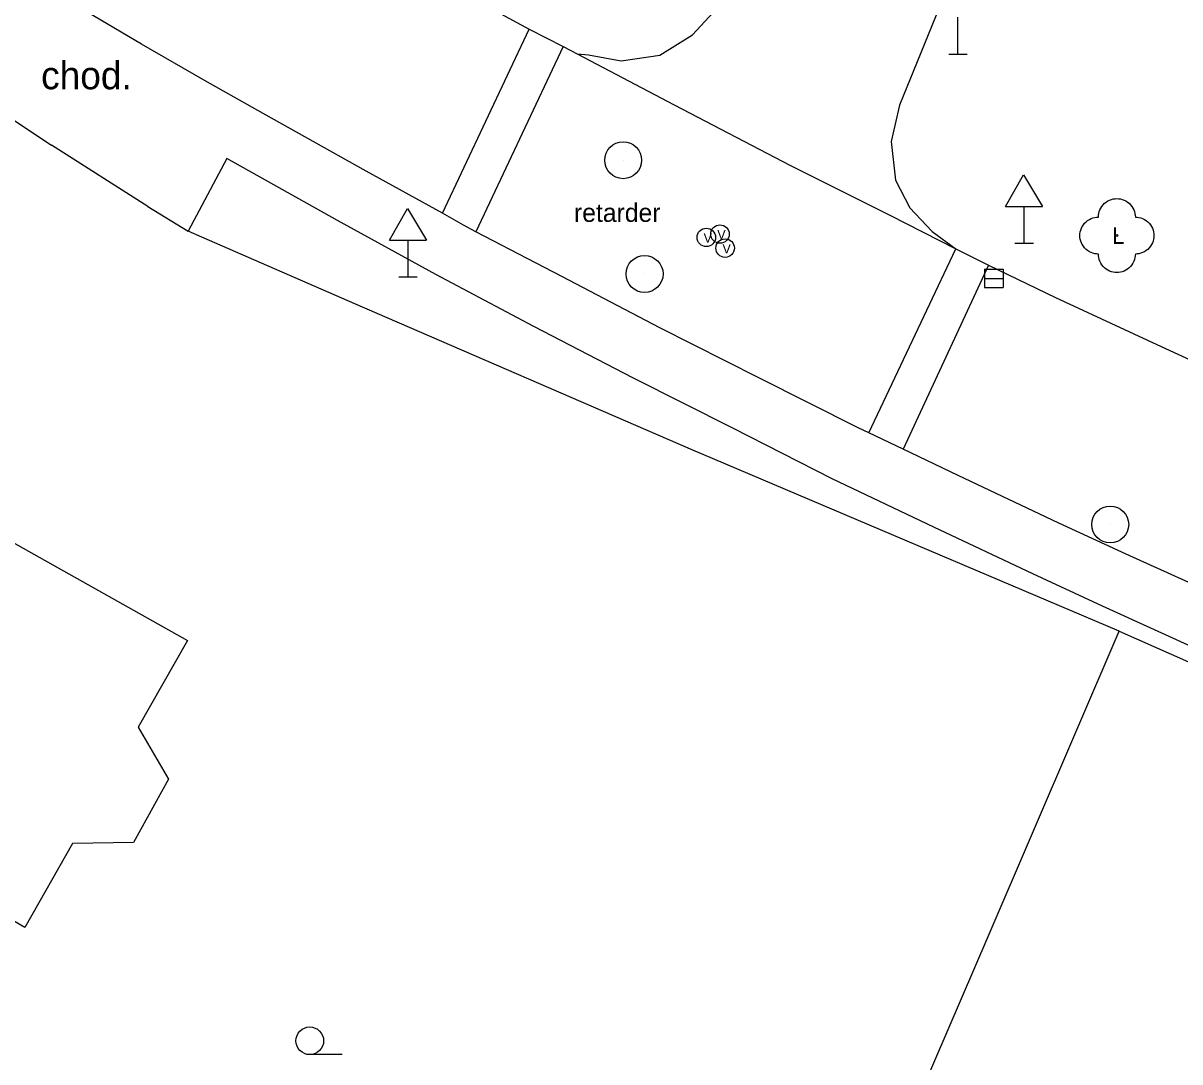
# Model space of a CAD drawing. Extents: x -836568 to -836015, y -1070547 to -1070212.
# Drawn here: x -836423.06 to -836391.76, y -1070409.55 to -1070381.44 of the extents above; entities that cross this region are included whole.
import ezdxf

# ---------------------------------------------------------------- set-up
doc = ezdxf.new("R2010")
doc.units = 0
for name, color, linetype in [('BodPole_mer', 7, 'Continuous'), ('Budovy_hranice', 7, 'Continuous'), ('Doprava_body', 7, 'Continuous'), ('Doprava_hranice', 7, 'Continuous'), ('Doprava_kody', 7, 'Continuous'), ('Doprava_popis', 7, 'Continuous'), ('OstPloch_kody', 7, 'Continuous'), ('PovrZnIS_body', 7, 'Continuous'), ('Stavby_linie', 7, 'Continuous'), ('Zelen_body', 7, 'Continuous')]:
    doc.layers.add(name, color=color, linetype=linetype)

msp = doc.modelspace()

# ---------------------------------------------------------------- linework, layer by layer
at = {"layer": 'BodPole_mer'}
for p, q in [((-836409.36, -1070381.6), (-836409.36, -1070381.6)), ((-836404.94, -1070381.76), (-836404.94, -1070381.76)), ((-836419.85, -1070382.01), (-836419.85, -1070382.01)), ((-836408.44, -1070382.07), (-836408.44, -1070382.07)), ((-836408.06, -1070382.27), (-836408.06, -1070382.27)), ((-836407.76, -1070382.3), (-836407.76, -1070382.3)), ((-836406.87, -1070382.46), (-836406.87, -1070382.46)), ((-836405.83, -1070382.31), (-836405.83, -1070382.31)), ((-836397.76, -1070382.28), (-836397.76, -1070382.28)), ((-836418.13, -1070383), (-836418.13, -1070383)), ((-836405.44, -1070383.65), (-836405.44, -1070383.65)), ((-836399.34, -1070383.66), (-836399.34, -1070383.66)), ((-836416.56, -1070383.89), (-836416.56, -1070383.89)), ((-836399.57, -1070384.64), (-836399.57, -1070384.64)), ((-836422.29, -1070384.74), (-836422.29, -1070384.74)), ((-836417.54, -1070385.1), (-836417.54, -1070385.1)), ((-836406.82, -1070385.15), (-836406.82, -1070385.15)), ((-836402.29, -1070385.29), (-836402.29, -1070385.29)), ((-836413.77, -1070385.45), (-836413.77, -1070385.45)), ((-836399.45, -1070385.69), (-836399.45, -1070385.69)), ((-836419.68, -1070386.4), (-836419.68, -1070386.4)), ((-836419.68, -1070386.4), (-836419.68, -1070386.4)), ((-836399.06, -1070386.44), (-836399.06, -1070386.44)), ((-836414.55, -1070386.78), (-836414.55, -1070386.78)), ((-836411.71, -1070386.58), (-836411.71, -1070386.58)), ((-836399.6, -1070386.64), (-836399.6, -1070386.64)), ((-836418.59, -1070387.07), (-836418.59, -1070387.07)), ((-836411.14, -1070386.91), (-836411.14, -1070386.91)), ((-836410.81, -1070387.09), (-836410.81, -1070387.09)), ((-836404.2, -1070387.15), (-836404.2, -1070387.15)), ((-836398.46, -1070387.08), (-836398.46, -1070387.08)), ((-836418.22, -1070387.23), (-836418.22, -1070387.23)), ((-836404.57, -1070387.24), (-836404.57, -1070387.24)), ((-836395.97, -1070387.4), (-836395.97, -1070387.4)), ((-836393.46, -1070387.19), (-836393.46, -1070387.19)), ((-836404.06, -1070387.53), (-836404.06, -1070387.53)), ((-836397.82, -1070387.55), (-836397.82, -1070387.55)), ((-836396.93, -1070387.99), (-836396.93, -1070387.99)), ((-836412.64, -1070388.31), (-836412.64, -1070388.31)), ((-836411.89, -1070388.24), (-836411.89, -1070388.24)), ((-836408.48, -1070388.3), (-836408.48, -1070388.3)), ((-836406.24, -1070388.23), (-836406.24, -1070388.23)), ((-836396.79, -1070388.35), (-836396.79, -1070388.35)), ((-836414.08, -1070389.04), (-836414.08, -1070389.04)), ((-836395.12, -1070388.87), (-836395.12, -1070388.87)), ((-836409.24, -1070389.65), (-836409.24, -1070389.65)), ((-836405.83, -1070389.69), (-836405.83, -1070389.69)), ((-836392.38, -1070390.14), (-836392.38, -1070390.14)), ((-836406.54, -1070391.05), (-836406.54, -1070391.05)), ((-836403.15, -1070391.04), (-836403.15, -1070391.04)), ((-836403.85, -1070392.4), (-836403.85, -1070392.4)), ((-836400.46, -1070392.39), (-836400.46, -1070392.39)), ((-836400.17, -1070392.53), (-836400.17, -1070392.53)), ((-836405, -1070392.97), (-836405, -1070392.97)), ((-836399.24, -1070392.97), (-836399.24, -1070392.97)), ((-836397.75, -1070393.68), (-836397.75, -1070393.68)), ((-836401.16, -1070393.77), (-836401.16, -1070393.77)), ((-836395.03, -1070394.97), (-836395.03, -1070394.97)), ((-836393.64, -1070395.01), (-836393.64, -1070395.01)), ((-836398.41, -1070395.08), (-836398.41, -1070395.08)), ((-836393.21, -1070395.81), (-836393.21, -1070395.81)), ((-836395.73, -1070396.35), (-836395.73, -1070396.35)), ((-836393.85, -1070397.22), (-836393.85, -1070397.22)), ((-836393.4, -1070397.9), (-836393.4, -1070397.9)), ((-836418.61, -1070398.15), (-836418.61, -1070398.15)), ((-836419.94, -1070400.5), (-836419.94, -1070400.5)), ((-836419.12, -1070401.9), (-836419.12, -1070401.9)), ((-836421.72, -1070403.64), (-836421.72, -1070403.64)), ((-836420.07, -1070403.62), (-836420.07, -1070403.62)), ((-836423.01, -1070405.92), (-836423.01, -1070405.92)), ((-836396.94, -1070406.16), (-836396.94, -1070406.16))]:
    msp.add_line(p, q, dxfattribs=at)
at = {"layer": 'Budovy_hranice'}
msp.add_lwpolyline([(-836427.22, -1070393.31), (-836418.61, -1070398.15), (-836419.94, -1070400.5), (-836419.12, -1070401.9), (-836420.07, -1070403.62), (-836421.72, -1070403.64), (-836423.01, -1070405.92), (-836423.64, -1070405.55), (-836424.86, -1070406.28), (-836427.06, -1070405.06), (-836427.09, -1070403.54), (-836435.26, -1070398.78), (-836432.13, -1070393.14), (-836428.33, -1070395.3), (-836427.22, -1070393.31)], dxfattribs=at)
at = {"layer": 'Doprava_body'}
for p, q in [((-836397.76, -1070382.28), (-836397.76, -1070381.28)), ((-836398.01, -1070382.28), (-836397.51, -1070382.28)), ((-836396.47, -1070386.4), (-836395.989, -1070385.546)), ((-836395.989, -1070385.546), (-836395.47, -1070386.4)), ((-836413.14, -1070387.31), (-836412.659, -1070386.456)), ((-836412.659, -1070386.456), (-836412.14, -1070387.31)), ((-836396.47, -1070386.4), (-836395.47, -1070386.4)), ((-836395.97, -1070387.4), (-836395.97, -1070386.4)), ((-836413.14, -1070387.31), (-836412.14, -1070387.31)), ((-836412.64, -1070388.31), (-836412.64, -1070387.31)), ((-836396.22, -1070387.4), (-836395.72, -1070387.4)), ((-836412.89, -1070388.31), (-836412.39, -1070388.31))]:
    msp.add_line(p, q, dxfattribs=at)
at = {"layer": 'Doprava_hranice'}
for p, q in [((-836411.71, -1070386.58), (-836409.36, -1070381.6)), ((-836408.44, -1070382.07), (-836410.81, -1070387.09)), ((-836400.17, -1070392.53), (-836397.82, -1070387.55)), ((-836396.93, -1070387.99), (-836399.24, -1070392.97))]:
    msp.add_line(p, q, dxfattribs=at)
for points in [[(-836396.26, -1070376.08), (-836399.34, -1070383.66), (-836399.57, -1070384.64), (-836399.45, -1070385.69), (-836399.06, -1070386.44), (-836398.46, -1070387.08), (-836397.82, -1070387.55), (-836396.93, -1070387.99)], [(-836399.24, -1070392.97), (-836400.17, -1070392.53), (-836400.46, -1070392.39), (-836403.15, -1070391.04), (-836405.83, -1070389.69), (-836408.48, -1070388.3), (-836410.81, -1070387.09), (-836411.14, -1070386.91), (-836411.71, -1070386.58), (-836413.77, -1070385.45), (-836416.56, -1070383.89), (-836418.13, -1070383), (-836419.85, -1070382.01), (-836422.05, -1070380.7), (-836424.17, -1070379.44)], [(-836410.46, -1070381.01), (-836409.36, -1070381.6), (-836408.44, -1070382.07), (-836408.06, -1070382.27), (-836407.76, -1070382.3), (-836406.87, -1070382.46), (-836405.83, -1070382.31), (-836404.94, -1070381.76), (-836404.38, -1070381.15)], [(-836408.06, -1070382.27), (-836405.44, -1070383.65), (-836402.29, -1070385.29), (-836399.6, -1070386.64), (-836397.82, -1070387.55)], [(-836354.29, -1070413.6), (-836369.6, -1070407.37), (-836381.91, -1070402.37), (-836385.59, -1070400.85), (-836388.36, -1070399.67), (-836391.13, -1070398.46), (-836393.85, -1070397.22), (-836395.73, -1070396.35), (-836398.41, -1070395.08), (-836401.16, -1070393.77), (-836403.85, -1070392.4), (-836406.54, -1070391.05), (-836409.24, -1070389.65), (-836411.89, -1070388.24), (-836414.55, -1070386.78), (-836417.54, -1070385.1), (-836418.59, -1070387.07)], [(-836396.93, -1070387.99), (-836395.12, -1070388.87), (-836392.38, -1070390.14), (-836389.65, -1070391.39), (-836386.89, -1070392.61), (-836384.17, -1070393.78), (-836382.29, -1070394.58), (-836379.84, -1070395.6), (-836379.24, -1070395.86), (-836376.76, -1070396.89), (-836369.55, -1070399.81), (-836361.91, -1070402.91), (-836351.68, -1070407.06)], [(-836294.78, -1070436.14), (-836298.75, -1070434.54), (-836300.99, -1070433.61), (-836301.95, -1070433.21), (-836302.68, -1070432.9), (-836308.94, -1070430.38), (-836313.57, -1070428.51), (-836318.21, -1070426.63), (-836324.7, -1070423.98), (-836329.32, -1070422.08), (-836333.96, -1070420.19), (-836342.84, -1070416.58), (-836353.67, -1070412.18), (-836369.06, -1070405.92), (-836381.28, -1070400.95), (-836385.01, -1070399.41), (-836387.75, -1070398.25), (-836390.49, -1070397.04), (-836393.21, -1070395.81), (-836395.03, -1070394.97), (-836397.75, -1070393.68), (-836399.24, -1070392.97)]]:
    msp.add_lwpolyline(points, dxfattribs=at)
at = {"layer": 'OstPloch_kody'}
msp.add_line((-836414.425, -1070409.36), (-836415.3, -1070409.36), dxfattribs=at)
msp.add_ellipse((-836415.3, -1070408.985), major_axis=(0.375, 0), ratio=0.999999, dxfattribs=at)
at = {"layer": 'PovrZnIS_body'}
for p, q in [((-836397.04, -1070388.1), (-836396.54, -1070388.1)), ((-836397.04, -1070388.1), (-836397.04, -1070388.6)), ((-836396.54, -1070388.1), (-836396.54, -1070388.6)), ((-836397.04, -1070388.35), (-836396.54, -1070388.35)), ((-836397.04, -1070388.6), (-836396.54, -1070388.6))]:
    msp.add_line(p, q, dxfattribs=at)
for centre, radius in [((-836406.82, -1070385.15), 0.5), ((-836404.57, -1070387.24), 0.25), ((-836404.2, -1070387.15), 0.25), ((-836404.06, -1070387.53), 0.25), ((-836406.24, -1070388.23), 0.5), ((-836393.64, -1070395.01), 0.5)]:
    msp.add_circle(centre, radius, dxfattribs=at)
at = {"layer": 'Stavby_linie'}
for p, q in [((-836425.81, -1070382.43), (-836422.29, -1070384.74)), ((-836419.68, -1070386.4), (-836422.29, -1070384.74)), ((-836419.68, -1070386.4), (-836422.29, -1070384.74)), ((-836419.68, -1070386.4), (-836418.59, -1070387.07)), ((-836419.68, -1070386.4), (-836418.59, -1070387.07)), ((-836393.4, -1070397.9), (-836390.82, -1070399.04))]:
    msp.add_line(p, q, dxfattribs=at)
for points in [[(-836393.4, -1070397.9), (-836405, -1070392.97), (-836414.08, -1070389.04), (-836418.22, -1070387.23), (-836418.59, -1070387.07)], [(-836407.72, -1070434.26), (-836404.42, -1070424.71), (-836401.63, -1070417.07), (-836396.94, -1070406.16), (-836393.4, -1070397.9)]]:
    msp.add_lwpolyline(points, dxfattribs=at)
at = {"layer": 'Zelen_body'}
msp.add_line((-836393.46, -1070387.19), (-836393.46, -1070387.19), dxfattribs=at)
for points in [[(-836393.96, -1070386.69), (-836393.958, -1070386.642), (-836393.95, -1070386.593), (-836393.938, -1070386.543), (-836393.92, -1070386.494), (-836393.896, -1070386.445), (-836393.867, -1070386.399), (-836393.833, -1070386.356), (-836393.794, -1070386.317), (-836393.751, -1070386.283), (-836393.705, -1070386.254), (-836393.656, -1070386.23), (-836393.607, -1070386.212), (-836393.557, -1070386.2), (-836393.508, -1070386.192), (-836393.46, -1070386.19), (-836393.412, -1070386.192), (-836393.363, -1070386.2), (-836393.313, -1070386.212), (-836393.264, -1070386.23), (-836393.215, -1070386.254), (-836393.169, -1070386.283), (-836393.126, -1070386.317), (-836393.087, -1070386.356), (-836393.053, -1070386.399), (-836393.024, -1070386.445), (-836393, -1070386.494), (-836392.982, -1070386.543), (-836392.97, -1070386.593), (-836392.962, -1070386.642), (-836392.96, -1070386.69)], [(-836393.96, -1070387.69), (-836394.008, -1070387.688), (-836394.057, -1070387.68), (-836394.107, -1070387.668), (-836394.156, -1070387.65), (-836394.205, -1070387.626), (-836394.251, -1070387.597), (-836394.294, -1070387.563), (-836394.333, -1070387.524), (-836394.367, -1070387.481), (-836394.396, -1070387.435), (-836394.42, -1070387.386), (-836394.438, -1070387.337), (-836394.45, -1070387.287), (-836394.458, -1070387.238), (-836394.46, -1070387.19), (-836394.458, -1070387.142), (-836394.45, -1070387.093), (-836394.438, -1070387.043), (-836394.42, -1070386.994), (-836394.396, -1070386.945), (-836394.367, -1070386.899), (-836394.333, -1070386.856), (-836394.294, -1070386.817), (-836394.251, -1070386.783), (-836394.205, -1070386.754), (-836394.156, -1070386.73), (-836394.107, -1070386.712), (-836394.057, -1070386.7), (-836394.008, -1070386.692), (-836393.96, -1070386.69)], [(-836392.96, -1070386.69), (-836392.912, -1070386.692), (-836392.863, -1070386.7), (-836392.813, -1070386.712), (-836392.764, -1070386.73), (-836392.715, -1070386.754), (-836392.669, -1070386.783), (-836392.626, -1070386.817), (-836392.587, -1070386.856), (-836392.553, -1070386.899), (-836392.524, -1070386.945), (-836392.5, -1070386.994), (-836392.482, -1070387.043), (-836392.47, -1070387.093), (-836392.462, -1070387.142), (-836392.46, -1070387.19), (-836392.462, -1070387.238), (-836392.47, -1070387.287), (-836392.482, -1070387.337), (-836392.5, -1070387.386), (-836392.524, -1070387.435), (-836392.553, -1070387.481), (-836392.587, -1070387.524), (-836392.626, -1070387.563), (-836392.669, -1070387.597), (-836392.715, -1070387.626), (-836392.764, -1070387.65), (-836392.813, -1070387.668), (-836392.863, -1070387.68), (-836392.912, -1070387.688), (-836392.96, -1070387.69)], [(-836392.96, -1070387.69), (-836392.962, -1070387.738), (-836392.97, -1070387.787), (-836392.982, -1070387.837), (-836393, -1070387.886), (-836393.024, -1070387.935), (-836393.053, -1070387.981), (-836393.087, -1070388.024), (-836393.126, -1070388.063), (-836393.169, -1070388.097), (-836393.215, -1070388.126), (-836393.264, -1070388.15), (-836393.313, -1070388.168), (-836393.363, -1070388.18), (-836393.412, -1070388.188), (-836393.46, -1070388.19), (-836393.508, -1070388.188), (-836393.557, -1070388.18), (-836393.607, -1070388.168), (-836393.656, -1070388.15), (-836393.705, -1070388.126), (-836393.751, -1070388.097), (-836393.794, -1070388.063), (-836393.833, -1070388.024), (-836393.867, -1070387.981), (-836393.896, -1070387.935), (-836393.92, -1070387.886), (-836393.938, -1070387.837), (-836393.95, -1070387.787), (-836393.958, -1070387.738), (-836393.96, -1070387.69)]]:
    msp.add_lwpolyline(points, dxfattribs=at)
msp.add_ellipse((-836393.46, -1070387.19), major_axis=(0.025, 0), ratio=0.999997, dxfattribs=at)

# ---------------------------------------------------------------- texts
at = {"layer": 'Doprava_kody'}
msp.add_text('chod.', height=0.75, dxfattribs=at).set_placement((-836422.57, -1070383.23))
at = {"layer": 'Doprava_popis'}
msp.add_text('retarder', height=0.5, dxfattribs=at).set_placement((-836408.15, -1070386.82))
at = {"layer": 'PovrZnIS_body'}
for p in [(-836404.641, -1070387.383), (-836404.271, -1070387.293), (-836404.131, -1070387.673)]:
    msp.add_text('V', height=0.25, dxfattribs=at).set_placement(p)
at = {"layer": 'Zelen_body'}
msp.add_text('L', height=0.45, dxfattribs=at).set_placement((-836393.591, -1070387.415))

doc.saveas('drawing.dxf')
